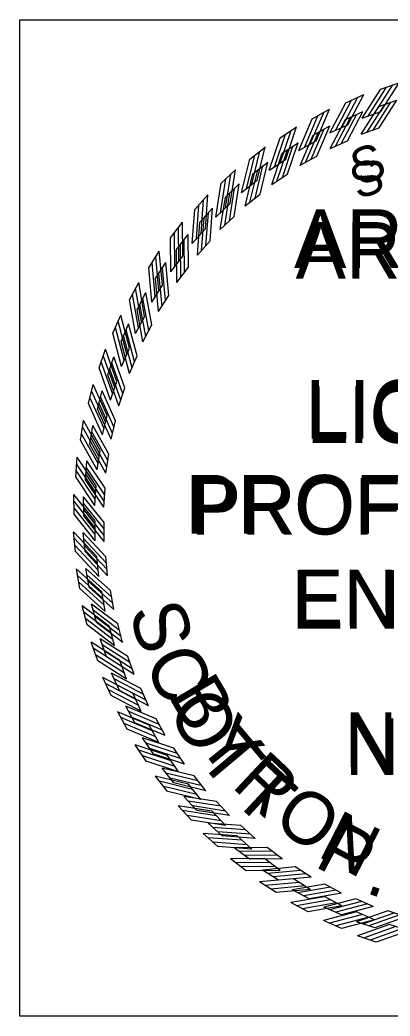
# Model space of a CAD drawing. Extents: x 0 to 1228740, y 0 to 152440.
# Drawn here: x 34.672 to 35.691, y 22.317 to 25.058 of the extents above; entities that cross this region are included whole.
import ezdxf

# ---------------------------------------------------------------- set-up
doc = ezdxf.new("R2010")
doc.units = 0
for name, color, linetype in [('R_No Plot', 7, 'Continuous'), ('STAMP', 7, 'Continuous'), ('STAMP_PP', 7, 'Continuous')]:
    doc.layers.add(name, color=color, linetype=linetype)

msp = doc.modelspace()

# ---------------------------------------------------------------- linework, layer by layer
at = {"layer": 'R_No Plot'}
msp.add_lwpolyline([(34.6722, 25.0583), (37.4139, 25.0583), (37.4139, 22.3166), (34.6722, 22.3166)], close=True, dxfattribs=at)
at = {"layer": 'STAMP'}
for p, q in [((35.6607, 24.8198), (35.7101, 24.8373)), ((35.5685, 24.7844), (35.6162, 24.8059)), ((35.4795, 24.7415), (35.5253, 24.7668)), ((35.6118, 24.7434), (35.6613, 24.7609)), ((35.3944, 24.6913), (35.438, 24.7204)), ((35.5261, 24.7042), (35.574, 24.7258)), ((35.4439, 24.6581), (35.4899, 24.6835)), ((35.3137, 24.6344), (35.3547, 24.6669)), ((35.3658, 24.6053), (35.4095, 24.6344)), ((35.238, 24.5709), (35.2762, 24.6067)), ((35.2923, 24.5462), (35.3335, 24.5789)), ((35.1678, 24.5014), (35.2029, 24.5403)), ((35.224, 24.4813), (35.2623, 24.5172)), ((35.1036, 24.4264), (35.1354, 24.468)), ((35.1612, 24.411), (35.1964, 24.4499)), ((35.0457, 24.3463), (35.074, 24.3904)), ((35.1045, 24.3357), (35.1364, 24.3774)), ((34.9948, 24.2617), (35.0193, 24.308)), ((35.0541, 24.256), (35.0825, 24.3002)), ((34.9509, 24.1731), (34.9715, 24.2213)), ((35.0106, 24.1724), (35.0352, 24.2188)), ((34.9145, 24.0813), (34.9311, 24.131)), ((34.9741, 24.0855), (34.9947, 24.1337)), ((34.9448, 23.9958), (34.9614, 24.0457)), ((34.8859, 23.9868), (34.8983, 24.0377)), ((34.8651, 23.8902), (34.8733, 23.942)), ((34.9231, 23.9041), (34.9356, 23.9551)), ((34.9091, 23.8109), (34.9172, 23.8628)), ((34.8524, 23.7922), (34.8562, 23.8445)), ((34.8478, 23.6936), (34.8473, 23.746)), ((34.9028, 23.7168), (34.9066, 23.7692)), ((34.9042, 23.6226), (34.9037, 23.6751)), ((34.8514, 23.5948), (34.8466, 23.647)), ((34.9135, 23.5288), (34.9087, 23.5811)), ((34.8631, 23.4968), (34.854, 23.5484)), ((34.9304, 23.436), (34.9213, 23.4878)), ((34.8829, 23.4), (34.8695, 23.4507)), ((34.955, 23.345), (34.9416, 23.3958)), ((34.9106, 23.3052), (34.8931, 23.3546)), ((34.987, 23.2563), (34.9695, 23.3059)), ((34.946, 23.213), (34.9245, 23.2608)), ((35.0262, 23.1706), (35.0047, 23.2185)), ((34.9889, 23.124), (34.9636, 23.1699)), ((35.0724, 23.0884), (35.0469, 23.1344)), ((35.0391, 23.0389), (35.01, 23.0825)), ((35.1251, 23.0103), (35.096, 23.054)), ((35.0961, 22.9582), (35.0635, 22.9993)), ((35.1842, 22.9368), (35.1516, 22.978)), ((35.1595, 22.8825), (35.1237, 22.9207)), ((35.2491, 22.8685), (35.2132, 22.9068)), ((35.229, 22.8123), (35.1901, 22.8474)), ((35.3195, 22.8057), (35.2805, 22.8409)), ((35.3041, 22.7481), (35.2624, 22.7799)), ((35.3947, 22.749), (35.353, 22.7809)), ((35.3842, 22.6903), (35.34, 22.7185)), ((35.4745, 22.6987), (35.4302, 22.727)), ((35.5581, 22.6551), (35.5116, 22.6797)), ((35.4688, 22.6393), (35.4224, 22.6638)), ((35.645, 22.6186), (35.5967, 22.6392)), ((35.5573, 22.5954), (35.5091, 22.616)), ((35.7346, 22.5894), (35.6848, 22.606)), ((35.6491, 22.5591), (35.5994, 22.5756))]:
    msp.add_line(p, q, dxfattribs=at)
for points in [[(35.6118, 24.7434), (35.6606, 24.8198)], [(35.6277, 24.7488), (35.6766, 24.8252)], [(35.6448, 24.7553), (35.6936, 24.8317)], [(35.6613, 24.761), (35.7101, 24.8374)], [(35.5415, 24.7109), (35.5838, 24.7911)], [(35.5579, 24.7188), (35.6003, 24.7989)], [(35.5739, 24.7258), (35.6163, 24.8059)], [(35.4744, 24.6752), (35.51, 24.7586)], [(35.4898, 24.6835), (35.5254, 24.7669)], [(35.5261, 24.7041), (35.5684, 24.7843)], [(35.4439, 24.658), (35.4794, 24.7414)], [(35.4587, 24.666), (35.4943, 24.7494)], [(35.3948, 24.6249), (35.4234, 24.7109)], [(35.4094, 24.6344), (35.438, 24.7205)], [(35.3658, 24.6052), (35.3943, 24.6913)], [(35.3799, 24.6144), (35.4085, 24.7005)], [(35.3196, 24.5681), (35.341, 24.6563)], [(35.3334, 24.5789), (35.3548, 24.667)], [(35.2923, 24.5461), (35.3137, 24.6343)], [(35.3056, 24.5565), (35.327, 24.6446)], [(35.2494, 24.5054), (35.2634, 24.595)], [(35.2622, 24.5172), (35.2762, 24.6068)], [(35.224, 24.4812), (35.238, 24.5708)], [(35.2364, 24.4926), (35.2504, 24.5822)], [(35.1964, 24.4499), (35.2029, 24.5403)], [(35.1726, 24.4233), (35.1792, 24.5137)], [(35.1845, 24.4371), (35.1911, 24.5275)], [(35.1612, 24.4109), (35.1678, 24.5013)], [(35.1363, 24.3774), (35.1354, 24.4681)], [(35.1148, 24.3489), (35.1139, 24.4396)], [(35.1256, 24.3636), (35.1246, 24.4543)], [(35.1045, 24.3356), (35.1036, 24.4263)], [(35.0729, 24.2856), (35.0645, 24.3758)], [(35.0824, 24.3002), (35.074, 24.3904)], [(35.0634, 24.27), (35.055, 24.3603)], [(35.0542, 24.2559), (35.0457, 24.3462)], [(35.0268, 24.2034), (35.0109, 24.2927)], [(35.0351, 24.2188), (35.0193, 24.308)], [(35.0186, 24.1871), (35.0028, 24.2764)], [(35.0106, 24.1723), (34.9948, 24.2616)], [(34.9947, 24.1337), (34.9715, 24.2214)], [(34.9809, 24.1008), (34.9577, 24.1885)], [(34.9876, 24.1177), (34.9645, 24.2054)], [(34.9741, 24.0854), (34.9509, 24.173)], [(34.9614, 24.0456), (34.9311, 24.1311)], [(34.9557, 24.0291), (34.9254, 24.1146)], [(34.9449, 23.9958), (34.9146, 24.0812)], [(34.9504, 24.0117), (34.92, 24.0972)], [(34.9312, 23.9382), (34.894, 24.0208)], [(34.9355, 23.9551), (34.8982, 24.0377)], [(34.9273, 23.9204), (34.89, 24.003)], [(34.9232, 23.904), (34.8859, 23.9867)], [(34.9172, 23.8627), (34.8732, 23.942)], [(34.9143, 23.8455), (34.8704, 23.9248)], [(34.9091, 23.8108), (34.8651, 23.8901)], [(34.9119, 23.8274), (34.8679, 23.9067)], [(34.9051, 23.7518), (34.8548, 23.8272)], [(34.9066, 23.7691), (34.8562, 23.8445)], [(34.9042, 23.7336), (34.8538, 23.809)], [(34.9028, 23.7168), (34.8524, 23.7922)], [(34.9037, 23.675), (34.8473, 23.746)], [(34.9037, 23.6576), (34.8473, 23.7286)], [(34.9043, 23.6394), (34.8479, 23.7104)], [(34.9043, 23.6225), (34.8479, 23.6935)], [(34.9086, 23.581), (34.8465, 23.6471)], [(34.9101, 23.5636), (34.848, 23.6297)], [(34.9121, 23.5455), (34.85, 23.6116)], [(34.9135, 23.5287), (34.8514, 23.5948)], [(34.9213, 23.4877), (34.854, 23.5484)], [(34.9242, 23.4705), (34.8568, 23.5312)], [(34.9277, 23.4526), (34.8604, 23.5133)], [(34.9305, 23.436), (34.8632, 23.4967)], [(34.9416, 23.3957), (34.8695, 23.4507)], [(34.9459, 23.3788), (34.8738, 23.4338)], [(34.9509, 23.3613), (34.8788, 23.4163)], [(34.9551, 23.345), (34.8829, 23.3999)], [(34.9695, 23.3058), (34.8931, 23.3546)], [(34.9751, 23.2893), (34.8987, 23.3381)], [(34.9816, 23.2722), (34.9052, 23.3211)], [(34.9871, 23.2563), (34.9107, 23.3051)], [(35.0047, 23.2184), (34.9245, 23.2608)], [(35.0117, 23.2025), (34.9315, 23.2448)], [(35.0195, 23.186), (34.9393, 23.2284)], [(35.0263, 23.1706), (34.9461, 23.2129)], [(35.0469, 23.1343), (34.9635, 23.1699)], [(35.0552, 23.1189), (34.9718, 23.1545)], [(35.0644, 23.1032), (34.981, 23.1388)], [(35.0724, 23.0884), (34.989, 23.124)], [(35.096, 23.0539), (35.01, 23.0825)], [(35.1056, 23.0393), (35.0195, 23.0679)], [(35.116, 23.0244), (35.0299, 23.053)], [(35.1252, 23.0103), (35.0392, 23.0388)], [(35.1516, 22.9779), (35.0634, 22.9993)], [(35.1623, 22.9641), (35.0742, 22.9855)], [(35.1739, 22.9501), (35.0858, 22.9715)], [(35.1843, 22.9368), (35.0962, 22.9582)], [(35.2132, 22.9067), (35.1236, 22.9207)], [(35.225, 22.8939), (35.1354, 22.9079)], [(35.2378, 22.8809), (35.1482, 22.8949)], [(35.2492, 22.8685), (35.1596, 22.8825)], [(35.2805, 22.8409), (35.1901, 22.8474)], [(35.2934, 22.829), (35.2029, 22.8356)], [(35.3071, 22.8171), (35.2167, 22.8237)], [(35.3195, 22.8057), (35.2291, 22.8123)], [(35.353, 22.7808), (35.2624, 22.7799)], [(35.3668, 22.7701), (35.2761, 22.7691)], [(35.3815, 22.7593), (35.2908, 22.7584)], [(35.3948, 22.749), (35.3042, 22.7481)], [(35.4303, 22.7269), (35.34, 22.7185)], [(35.4449, 22.7174), (35.3546, 22.709)], [(35.4604, 22.7079), (35.3701, 22.6995)], [(35.4745, 22.6987), (35.3843, 22.6903)], [(35.5117, 22.6796), (35.4224, 22.6638)], [(35.527, 22.6713), (35.4377, 22.6555)], [(35.5433, 22.6631), (35.454, 22.6473)], [(35.5581, 22.6551), (35.4688, 22.6393)], [(35.5967, 22.6392), (35.509, 22.616)], [(35.6127, 22.6322), (35.525, 22.609)], [(35.6296, 22.6254), (35.5419, 22.6022)], [(35.645, 22.6186), (35.5574, 22.5954)], [(35.6848, 22.6059), (35.5993, 22.5756)], [(35.7013, 22.6002), (35.6159, 22.5699)], [(35.7187, 22.5949), (35.6333, 22.5645)], [(35.7347, 22.5894), (35.6492, 22.5591)]]:
    msp.add_lwpolyline(points, dxfattribs=at)
at = {"layer": 'STAMP_PP'}
for p, q in [((35.6651, 24.8673), (35.7164, 24.8855)), ((35.5694, 24.8305), (35.619, 24.8528)), ((35.477, 24.7859), (35.5246, 24.8123)), ((35.6144, 24.788), (35.6658, 24.8062)), ((35.3886, 24.7339), (35.4339, 24.7641)), ((35.5254, 24.7473), (35.5751, 24.7696)), ((35.3049, 24.6747), (35.3475, 24.7085)), ((35.4401, 24.6993), (35.4878, 24.7257)), ((35.359, 24.6445), (35.4043, 24.6748)), ((35.2263, 24.6088), (35.266, 24.6461)), ((35.2827, 24.5832), (35.3254, 24.6171)), ((35.1534, 24.5367), (35.1899, 24.5771)), ((35.2117, 24.5158), (35.2515, 24.5531)), ((35.0867, 24.4588), (35.1197, 24.502)), ((35.1466, 24.4428), (35.1831, 24.4833)), ((35.0267, 24.3756), (35.056, 24.4214)), ((35.0876, 24.3646), (35.1207, 24.408)), ((34.9737, 24.2878), (34.9992, 24.3359)), ((35.0354, 24.2819), (35.0648, 24.3278)), ((34.9282, 24.1959), (34.9496, 24.2459)), ((34.9902, 24.1951), (35.0157, 24.2433)), ((34.9522, 24.1048), (34.9737, 24.155)), ((34.8904, 24.1005), (34.9076, 24.1521)), ((34.8607, 24.0024), (34.8736, 24.0552)), ((34.9219, 24.0118), (34.9391, 24.0635)), ((34.8994, 23.9165), (34.9123, 23.9695)), ((34.8391, 23.9021), (34.8476, 23.9558)), ((34.8259, 23.8004), (34.8299, 23.8547)), ((34.8848, 23.8198), (34.8932, 23.8736)), ((34.8782, 23.7221), (34.8822, 23.7765)), ((34.8212, 23.6979), (34.8207, 23.7524)), ((34.8797, 23.6242), (34.8792, 23.6788)), ((34.8249, 23.5955), (34.8199, 23.6496)), ((34.8893, 23.5268), (34.8843, 23.5811)), ((34.837, 23.4936), (34.8276, 23.5472)), ((34.9069, 23.4306), (34.8975, 23.4843)), ((34.8576, 23.3931), (34.8437, 23.4458)), ((34.9325, 23.3361), (34.9186, 23.3888)), ((34.8863, 23.2947), (34.8682, 23.346)), ((34.9657, 23.244), (34.9475, 23.2954)), ((34.9231, 23.199), (34.9008, 23.2486)), ((35.0064, 23.155), (34.984, 23.2047)), ((34.9677, 23.1066), (34.9414, 23.1542)), ((35.0543, 23.0696), (35.0279, 23.1174)), ((35.0197, 23.0182), (34.9896, 23.0635)), ((35.1091, 22.9886), (35.0789, 23.0339)), ((35.0789, 22.9345), (35.0451, 22.9771)), ((35.1704, 22.9123), (35.1365, 22.955)), ((35.1448, 22.8559), (35.1076, 22.8955)), ((35.2378, 22.8413), (35.2005, 22.8811)), ((35.2169, 22.783), (35.1766, 22.8194)), ((35.3109, 22.7761), (35.2704, 22.8127)), ((35.2949, 22.7163), (35.2516, 22.7493)), ((35.389, 22.7172), (35.3457, 22.7503)), ((35.378, 22.6563), (35.3322, 22.6856)), ((35.4718, 22.665), (35.4259, 22.6944)), ((35.4659, 22.6033), (35.4178, 22.6288)), ((35.5586, 22.6198), (35.5104, 22.6453)), ((35.6488, 22.5818), (35.5987, 22.6033)), ((35.5578, 22.5578), (35.5078, 22.5792)), ((35.7419, 22.5515), (35.6901, 22.5687)), ((35.6531, 22.52), (35.6015, 22.5372))]:
    msp.add_line(p, q, dxfattribs=at)
for points in [[(35.6309, 24.7936), (35.6816, 24.8729)], [(35.6486, 24.8003), (35.6993, 24.8796)], [(35.6658, 24.8062), (35.7164, 24.8855)], [(35.5585, 24.7624), (35.6024, 24.8456)], [(35.5751, 24.7696), (35.619, 24.8529)], [(35.6144, 24.7879), (35.6651, 24.8672)], [(35.5254, 24.7472), (35.5693, 24.8304)], [(35.5414, 24.7542), (35.5854, 24.8375)], [(35.44, 24.6993), (35.477, 24.7859)], [(35.4554, 24.7076), (35.4924, 24.7942)], [(35.4718, 24.7171), (35.5087, 24.8037)], [(35.4877, 24.7257), (35.5246, 24.8123)], [(35.4043, 24.6748), (35.4339, 24.7641)], [(35.3589, 24.6445), (35.3886, 24.7338)], [(35.3736, 24.654), (35.4033, 24.7434)], [(35.3891, 24.6649), (35.4188, 24.7542)], [(35.3253, 24.6171), (35.3475, 24.7086)], [(35.2965, 24.5939), (35.3187, 24.6854)], [(35.311, 24.606), (35.3332, 24.6975)], [(35.2827, 24.5831), (35.3048, 24.6746)], [(35.2246, 24.5276), (35.2391, 24.6206)], [(35.2381, 24.5408), (35.2526, 24.6338)], [(35.2514, 24.5531), (35.266, 24.6461)], [(35.2117, 24.5157), (35.2262, 24.6088)], [(35.183, 24.4832), (35.1899, 24.5771)], [(35.1584, 24.4556), (35.1652, 24.5495)], [(35.1708, 24.4699), (35.1776, 24.5638)], [(35.1465, 24.4427), (35.1534, 24.5366)], [(35.1095, 24.3936), (35.1086, 24.4878)], [(35.1207, 24.4079), (35.1197, 24.5021)], [(35.0876, 24.3645), (35.0867, 24.4587)], [(35.0984, 24.3784), (35.0974, 24.4725)], [(35.0548, 24.3126), (35.0461, 24.4063)], [(35.0647, 24.3278), (35.056, 24.4215)], [(35.0354, 24.2818), (35.0267, 24.3755)], [(35.045, 24.2964), (35.0363, 24.3902)], [(35.007, 24.2273), (34.9905, 24.32)], [(35.0156, 24.2432), (34.9992, 24.3359)], [(34.9985, 24.2104), (34.9821, 24.3031)], [(34.9902, 24.195), (34.9737, 24.2877)], [(34.9736, 24.1549), (34.9496, 24.246)], [(34.9593, 24.1208), (34.9353, 24.2118)], [(34.9664, 24.1383), (34.9423, 24.2294)], [(34.9523, 24.1048), (34.9282, 24.1958)], [(34.9332, 24.0463), (34.9017, 24.1351)], [(34.9391, 24.0635), (34.9076, 24.1522)], [(34.9219, 24.0117), (34.8905, 24.1004)], [(34.9276, 24.0283), (34.8962, 24.117)], [(34.9122, 23.9695), (34.8735, 24.0553)], [(34.9037, 23.9334), (34.865, 24.0193)], [(34.9078, 23.9519), (34.8691, 24.0377)], [(34.8994, 23.9165), (34.8607, 24.0023)], [(34.8902, 23.8557), (34.8446, 23.938)], [(34.8932, 23.8736), (34.8476, 23.9559)], [(34.8877, 23.837), (34.842, 23.9193)], [(34.8848, 23.8197), (34.8392, 23.902)], [(34.8822, 23.7764), (34.8299, 23.8547)], [(34.8807, 23.7584), (34.8284, 23.8366)], [(34.8783, 23.722), (34.826, 23.8003)], [(34.8797, 23.7395), (34.8274, 23.8178)], [(34.8792, 23.6787), (34.8206, 23.7524)], [(34.8792, 23.6606), (34.8206, 23.7343)], [(34.8798, 23.6417), (34.8212, 23.7154)], [(34.8798, 23.6242), (34.8212, 23.6979)], [(34.8843, 23.5811), (34.8198, 23.6497)], [(34.8858, 23.563), (34.8213, 23.6316)], [(34.8879, 23.5442), (34.8235, 23.6128)], [(34.8894, 23.5268), (34.8249, 23.5954)], [(34.8975, 23.4842), (34.8275, 23.5472)], [(34.9004, 23.4663), (34.8305, 23.5294)], [(34.9041, 23.4478), (34.8342, 23.5108)], [(34.907, 23.4305), (34.8371, 23.4936)], [(34.9186, 23.3887), (34.8437, 23.4458)], [(34.923, 23.3712), (34.8481, 23.4282)], [(34.9282, 23.353), (34.8533, 23.4101)], [(34.9325, 23.336), (34.8576, 23.3931)], [(34.9475, 23.2953), (34.8681, 23.346)], [(34.9534, 23.2782), (34.874, 23.3289)], [(34.9601, 23.2605), (34.8807, 23.3112)], [(34.9657, 23.244), (34.8864, 23.2946)], [(34.984, 23.2047), (34.9008, 23.2486)], [(34.9913, 23.1881), (34.908, 23.232)], [(34.9994, 23.171), (34.9162, 23.2149)], [(35.0065, 23.155), (34.9232, 23.1989)], [(35.0279, 23.1173), (34.9413, 23.1542)], [(35.0365, 23.1014), (34.9499, 23.1383)], [(35.046, 23.085), (34.9594, 23.122)], [(35.0544, 23.0696), (34.9678, 23.1066)], [(35.0789, 23.0339), (34.9895, 23.0635)], [(35.0888, 23.0187), (34.9994, 23.0483)], [(35.0996, 23.0032), (35.0103, 23.0328)], [(35.1092, 22.9885), (35.0198, 23.0182)], [(35.1365, 22.9549), (35.045, 22.9771)], [(35.1477, 22.9406), (35.0562, 22.9628)], [(35.1597, 22.9261), (35.0682, 22.9482)], [(35.1705, 22.9122), (35.079, 22.9344)], [(35.2005, 22.881), (35.1075, 22.8956)], [(35.2128, 22.8677), (35.1198, 22.8822)], [(35.226, 22.8542), (35.133, 22.8687)], [(35.2379, 22.8413), (35.1449, 22.8558)], [(35.2704, 22.8126), (35.1765, 22.8194)], [(35.2838, 22.8004), (35.1899, 22.8072)], [(35.2981, 22.788), (35.2042, 22.7948)], [(35.3109, 22.7761), (35.217, 22.783)], [(35.3457, 22.7503), (35.2516, 22.7493)], [(35.36, 22.7391), (35.2659, 22.7382)], [(35.3753, 22.728), (35.2811, 22.727)], [(35.3891, 22.7172), (35.295, 22.7163)], [(35.4259, 22.6943), (35.3322, 22.6856)], [(35.4411, 22.6844), (35.3473, 22.6757)], [(35.4572, 22.6746), (35.3635, 22.6658)], [(35.4719, 22.665), (35.3781, 22.6563)], [(35.5104, 22.6452), (35.4177, 22.6288)], [(35.5264, 22.6366), (35.4337, 22.6201)], [(35.5433, 22.6281), (35.4506, 22.6117)], [(35.5587, 22.6198), (35.466, 22.6033)], [(35.5987, 22.6032), (35.5077, 22.5792)], [(35.6153, 22.5959), (35.5243, 22.5719)], [(35.6329, 22.5889), (35.5418, 22.5649)], [(35.6489, 22.5819), (35.5579, 22.5578)], [(35.6902, 22.5687), (35.6014, 22.5372)], [(35.7073, 22.5628), (35.6186, 22.5313)], [(35.7254, 22.5572), (35.6367, 22.5257)], [(35.7419, 22.5515), (35.6532, 22.5201)]]:
    msp.add_lwpolyline(points, dxfattribs=at)

# ---------------------------------------------------------------- texts
at = {"layer": 'STAMP'}
for s, height, rotation, p in [('S', 0.0953, 19.7726, (35.6026, 24.5629)), ('B', 0.1448, 300.7985, (35.079, 23.198)), ('Y', 0.1448, 308.8241, (35.1568, 23.0675)), ('R', 0.1448, 316.8497, (35.2521, 22.9491)), ('O', 0.1448, 324.8753, (35.3629, 22.8452)), ('N', 0.1448, 332.9009, (35.4872, 22.7578))]:
    msp.add_text(s, height=height, rotation=rotation, dxfattribs=at).set_placement(p)
for s, height, p in [('ARKANSAS', 0.15559, (35.4313, 24.3461)), ('LICENSED', 0.15559, (35.461, 23.8938)), ('PROFESSIONAL', 0.155594, (35.1424, 23.6419)), ('ENGINEER', 0.15559, (35.4239, 23.39)), ('No.13640', 0.15004, (35.5662, 23.0021))]:
    msp.add_text(s, height=height, dxfattribs=at).set_placement(p)
at = {"layer": 'STAMP_PP'}
for s, height, rotation, p in [('S', 0.099, 19.7726, (35.6048, 24.6006)), ('S', 0.1503, 286.9475, (34.9709, 23.4322)), ('C', 0.1503, 294.2435, (35.0127, 23.2951)), ('O', 0.1503, 301.9044, (35.075, 23.158)), ('T', 0.1503, 309.93, (35.1592, 23.0247)), ('T', 0.1503, 317.226, (35.2512, 22.9148)), ('P', 0.1503, 332.1828, (35.4793, 22.7305)), ('.', 0.1503, 340.2084, (35.6193, 22.6578))]:
    msp.add_text(s, height=height, rotation=rotation, dxfattribs=at).set_placement(p)
for s, height, p in [('ARKANSAS', 0.16155, (35.427, 24.3754)), ('LICENSED', 0.16155, (35.4578, 23.9059)), ('PROFESSIONAL', 0.161547, (35.127, 23.6443)), ('ENGINEER', 0.16155, (35.4193, 23.3828)), ('No.10887', 0.15578, (35.567, 22.98))]:
    msp.add_text(s, height=height, dxfattribs=at).set_placement(p)

doc.saveas('drawing.dxf')
